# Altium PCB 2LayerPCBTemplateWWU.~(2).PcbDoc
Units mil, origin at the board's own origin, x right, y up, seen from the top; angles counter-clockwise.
Board outline 716.1 x 716.1 mil, 2 copper layers (Top Layer, Bottom Layer); 10 components, 9 nets, 28 pads, 2 vias.
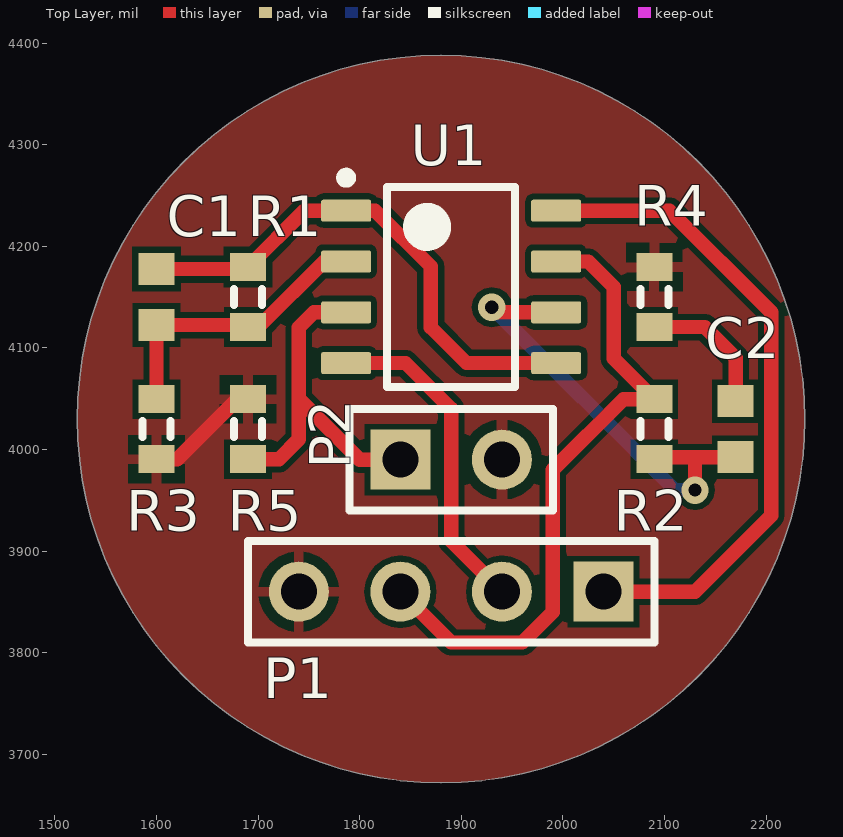
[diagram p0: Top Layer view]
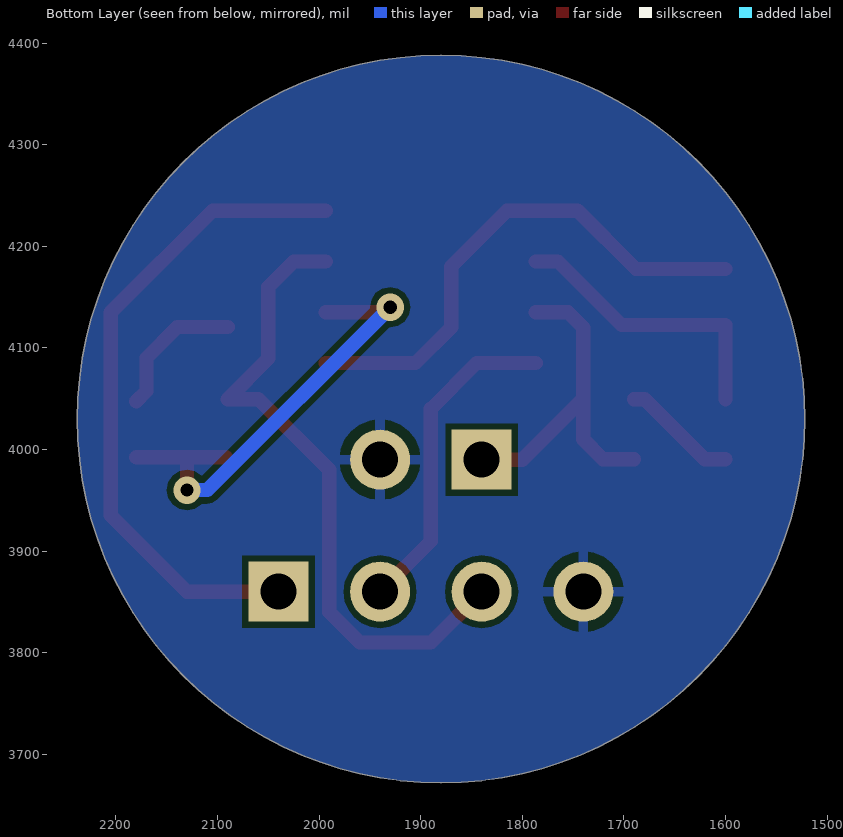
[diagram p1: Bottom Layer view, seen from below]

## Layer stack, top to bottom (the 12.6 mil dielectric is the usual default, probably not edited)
Top Solder: solder mask 0.4, Solder Resist, Dk 3.5
Top Layer: signal copper 1.4
Dielectric 1: dielectric 12.6, FR-4, Dk 4.8
Bottom Layer: signal copper 1.4
Bottom Solder: solder mask 0.4, Solder Resist, Dk 3.5

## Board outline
1880,3671.95 cw(c1880,4030) 1521.95,4030 cw(c1880,4030) 1880,4388.05 cw(c1880,4030) 2238.05,4030 cw(c1880,4030)

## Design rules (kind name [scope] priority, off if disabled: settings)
Clearance [All] p1: gap=6 ignorepadtopadclearanceinfootprint=FALSE except(0: Arc-Hole Track-Hole SMDPad-Hole THPad-Hole Via-Hole Fill-Hole Poly-Hole Region-Hole Text-Hole)
HoleSize [All] p1: absolutevalues=TRUE maxlimit=125 minlimit=13 maxpercent=80.000 minpercent=20.000
MinimumSolderMaskSliver [All] p1: minsoldermaskwidth=1
PolygonConnect [All] p1: connectstyle=Relief reliefconductorwidth=10 reliefentries=4 polygonreliefangle="90 Angle" airgapwidth=10
RoutingVias [All] p1: holewidth=13 width=20 viastyle="Through Hole" minholewidth=13 minwidth=20 maxholewidth=125 maxwidth=250
SilkToSilkClearance [All] p1: silktosilkclearance=4
SilkToSolderMaskClearance [IsPad] p1: minsilkscreentomaskgap=6 clearancetoexposedcopper=TRUE
SolderMaskExpansion [All] p1: expansion=4
Width [All] p1: maxlimit=500 minlimit=6 preferedwidth=25
26 further rules are at their usual default settings.

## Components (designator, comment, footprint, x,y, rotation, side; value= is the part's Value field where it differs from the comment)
C1 "Cap Semi" 1608[0603] 1600,4150 r90 top value=100pF
C2 "Cap Semi" 1608[0603] 2170,4020 r270 top value=100pF
P1 "Header 4" HDR1X4 2040,3860 r180 top
P2 "Header 2" HDR1X2 1840,3990 r0 top
R1 "Res3" J1-0603 1690,4150 r270 top value=10k
R2 "Res3" J1-0603 2090,4020 r270 top value=10k
R3 "Res3" J1-0603 1600,4020 r270 top value=1K
R4 "Res3" J1-0603 2090,4150 r90 top value=1K
R5 "Res3" J1-0603 1690,4020 r270 top value=2M
U1 "LF353M/NOPB" D0008A_L 1890,4160 r0 top

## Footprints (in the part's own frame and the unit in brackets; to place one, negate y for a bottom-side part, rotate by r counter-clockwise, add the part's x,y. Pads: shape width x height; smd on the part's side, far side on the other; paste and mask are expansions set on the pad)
1608[0603] [mm] "Chip Capacitor, Body 1.6x0.8mm, IPC High Density"
  rect 0.8x0.9 smd: 1(-0.7,0) 2(0.7,0)
  body extent -0.87,-0.48 0.87,0.48, height 1.3
D0008A_L [mm] "SOIC, 8-Leads, Body 5x4mm, Pitch 1.27mm, IPC High Density"
  rrect18% 1.25x0.55 smd: 1(-2.625,1.905) 2(-2.625,0.635) 3(-2.625,-0.635) 4(-2.625,-1.905) 5(2.625,-1.905) 6(2.625,-0.635) 7(2.625,0.635) 8(2.625,1.905)
  silkscreen extent -2.75,-2.5 1.6,2.85, body extent -3,-2.45 3,2.45, height 1.63
HDR1X2 [mm] "Connector; Header; 2 Position"
  rect 1.5x1.5 hole 0.9: 1(0,0)
  round 1.5 hole 0.9: 2(2.54,0)
  silkscreen extent -1.27,-1.27 3.81,1.27
HDR1X4 [mm] "Connector; Header; 4 Position"
  rect 1.5x1.5 hole 0.9: 1(0,0)
  round 1.5 hole 0.9: 2(2.54,0) 3(5.08,0) 4(7.62,0)
  silkscreen extent -1.27,-1.27 8.89,1.27
J1-0603 [mm] "Chip Resistor, Body 1.6x0.8mm, IPC High Density"
  rect 0.7x0.9 smd: 1(-0.75,0) 2(0.75,0)
  silkscreen extent -0.2,-0.35 0.2,0.35, body extent -0.85,-0.48 0.85,0.48, height 0.9

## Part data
C1 C2: "Capacitor (Semiconductor SIM Model)"
P1: "Header, 4-Pin"
P2: "Header, 2-Pin"
R1 R2 R3 R4 R5: "Resistor"
U1: library part CMP-0055-00856-3, "Wide Bandwidth Dual JFET Input Operational Amplifier, 8-pin Narrow SOIC, Pb-Free", Manufacturer="Texas Instruments", Package Reference=D0008A, PackageTopMarking=NSZXTT*LF353*M, PowerWise=N

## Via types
v1: diameter 27, hole 13, Top Layer to Bottom Layer, tented both sides, 2 vias

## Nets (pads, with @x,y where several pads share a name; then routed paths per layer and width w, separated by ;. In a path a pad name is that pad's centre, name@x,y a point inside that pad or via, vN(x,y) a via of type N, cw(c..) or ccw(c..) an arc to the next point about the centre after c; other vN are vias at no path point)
+12V: P1.1 U1.8 | length 649.1
  Top Layer w14: U1.8 2105,4235 2205,4135 2205,3935 2130,3860 P1.1
-12V: P1.2 U1.4 | length 322.7
  Top Layer w14: U1.4 1845,4085 1890,4040 1890,3910 P1.2
MIC+: P2.1 R5.2 U1.3 | length 345.8
  Top Layer w14: R5.2 1720.47,3990.47 1740,4010 1740,4050 ; U1.3 1755,4135 1740,4120 1740,4050 ; P2.1 1800,3990 1740,4050
MIC-: P1.4 P2.2 R3.2 R4.2 R5.1 | length 114.5
  Top Layer w14: R3.2 1620.47,3990.47 1679.53,4049.53 R5.1
NetC1_1: C1.1 R1.2 R3.1 U1.2 | length 285.5
  Top Layer w14: R3.1 C1.1 1702.44,4122.44 1765,4185 U1.2
NetC1_2: C1.2 R1.1 U1.1 U1.5 | length 511.6
  Top Layer w14: C1.2 R1.1@1688.03,4177.56 ; R1.1 1745.47,4235 U1.1 1815,4235 1870,4180 1870,4120 1905,4085 U1.5
NetC2_1: C2.1 R4.1 | length 139.2
  Top Layer w14: R4.1 2139.53,4120.47 2170,4090 2170,4057.56 C2.1@2180,4047.56
NetC2_2: C2.2 R2.2 U1.6 | length 460.4
  Top Layer w14: v1(1930,4140) 1935,4135 U1.6 ; R2.2@2091.97,3992.44 2130,3992.44 ; v1(2130,3960) 2130,3992.44 ; C2.2@2180,3992.44 2130,3992.44
  Bottom Layer w14: v1(1930,4140) 2110,3960 v1(2130,3960)
SIG_OUT: P1.3 R2.1 U1.7 | length 646
  Top Layer w14: P1.3 1890,3810 1960,3810 1990,3840 1990,3980 2059.53,4049.53 R2.1 2050,4089.53 2050,4160 2025,4185 U1.7

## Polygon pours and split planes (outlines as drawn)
MIC- on Top Layer "GND" (solid, pour order 5): 1880,3671.95 cw(c1880,4030) 1521.95,4030 cw(c1880,4030) 1880,4388.05 cw(c1880,4030) 2238.05,4030 cw(c1880,4030)
MIC- on Bottom Layer "GND" (solid, pour order 6): 1880,3671.95 cw(c1880,4030) 1521.95,4030 cw(c1880,4030) 1880,4388.05 cw(c1880,4030) 2238.05,4030 cw(c1880,4030)

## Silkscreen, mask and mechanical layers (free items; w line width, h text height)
Mechanical 3:
  circle w10: c1880,4030 r358.05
